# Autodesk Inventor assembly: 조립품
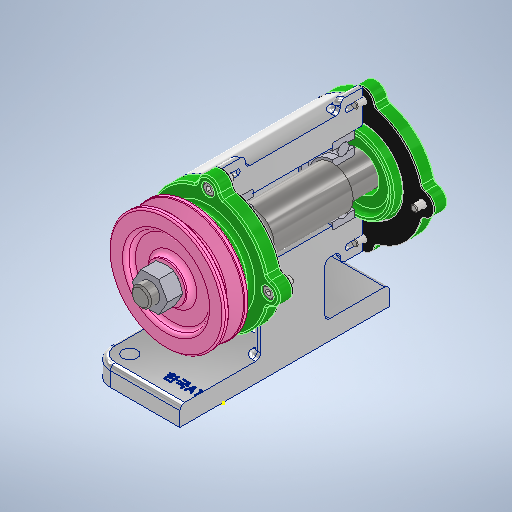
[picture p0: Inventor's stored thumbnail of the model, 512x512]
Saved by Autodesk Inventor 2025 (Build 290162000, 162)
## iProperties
Created: 2024-08
Part Number: 조립품
Document SubType Name: Assembly
Designer: Administrator
Author: Administrator
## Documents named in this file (12)
- C:\Users\Administrator\Desktop\740807V1001\조립품.iam
- C:\Users\Administrator\Desktop\740807V1001\본체.ipt
- C:\Users\Administrator\Desktop\740807V1001\뒤커버\뒤커버.ipt
- C:\Users\Administrator\Desktop\740807V1001\베어링 6204\베어링 6204.ipt
- C:\Users\Administrator\Desktop\740807V1001\개스킷\개스킷.ipt
- C:\Users\Administrator\Desktop\740807V1001\볼트 M4 x 12\볼트 M4 x 12.ipt
- C:\Users\Administrator\Desktop\740807V1001\앞커버\앞커버.ipt
- C:\Users\Administrator\Desktop\740807V1001\오일실\오일실.ipt
- C:\Users\Administrator\Desktop\740807V1001\축\축.ipt
- C:\Users\Administrator\Desktop\740807V1001\키 4 x 4\키 4 x 4.ipt
- C:\Users\Administrator\Desktop\740807V1001\V-벨트풀리\V-벨트풀리.ipt
- C:\Users\Administrator\Desktop\740807V1001\너트 M12 x 1.25\너트 M12 x 1.25.ipt
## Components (3 placed, 2 different names)
1. 개스킷:1
2. 개스킷:2
3. V-벨트풀리:1
